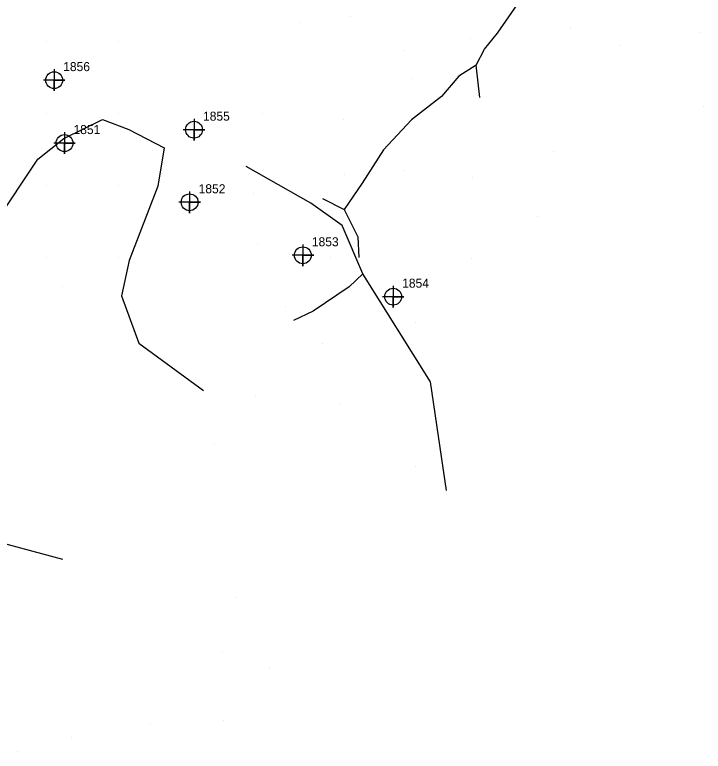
# Model space of a CAD drawing. Extents: x 2062781 to 2066835, y 358981 to 366501.
# Drawn here: x 2063986.2 to 2064177.3, y 360658.3 to 360862.8 of the extents above; entities that cross this region are included whole.
import ezdxf

# ---------------------------------------------------------------- set-up
doc = ezdxf.new("R2010")
doc.units = 0
for name, color, linetype in [('Exist DTM Regular Point CELL', 7, 'Continuous'), ('Exist DTM Regular Point Cogo Number', 7, 'Continuous'), ('PH Exist DTM Breakline', 7, 'Continuous'), ('PH Exist DTM Point', 7, 'Continuous')]:
    doc.layers.add(name, color=color, linetype=linetype)

msp = doc.modelspace()

# ---------------------------------------------------------------- linework, layer by layer
at = {"layer": 'Exist DTM Regular Point CELL'}
for points in [[(2063997.19, 360847.67), (2063997.19, 360841.67), (2063997.19, 360844.67), (2064000.19, 360844.67), (2063994.19, 360844.67)], [(2064036, 360833.91), (2064036, 360827.91), (2064036, 360830.91), (2064039, 360830.91), (2064033, 360830.91)], [(2064000.05, 360830.19), (2064000.05, 360824.19), (2064000.05, 360827.19), (2064003.05, 360827.19), (2063997.05, 360827.19)], [(2064034.78, 360813.76), (2064034.78, 360807.76), (2064034.78, 360810.76), (2064037.78, 360810.76), (2064031.78, 360810.76)], [(2064066.21, 360799.04), (2064066.21, 360793.04), (2064066.21, 360796.04), (2064069.21, 360796.04), (2064063.21, 360796.04)], [(2064091.27, 360787.55), (2064091.27, 360781.55), (2064091.27, 360784.55), (2064094.27, 360784.55), (2064088.27, 360784.55)]]:
    msp.add_lwpolyline(points, dxfattribs=at)
for centre in [(2063997.19, 360844.67), (2064036, 360830.91), (2064000.05, 360827.19), (2064034.78, 360810.76), (2064066.21, 360796.04), (2064091.27, 360784.55)]:
    msp.add_circle(centre, 2.34, dxfattribs=at)
at = {"layer": 'PH Exist DTM Breakline'}
for points in [[(2064115.35, 360839.89), (2064114.33, 360848.84), (2064116.6, 360853.22), (2064120.24, 360857.74), (2064126.5, 360866.73), (2064130.56, 360876.37)], [(2064114.33, 360848.84), (2064109.52, 360845.79), (2064104.7, 360840.08), (2064096.34, 360833.68), (2064088.55, 360825.34), (2064082.67, 360816.06), (2064077.65, 360808.79)], [(2063999.58, 360711.57), (2063972.79, 360718.76), (2063955.09, 360727.6), (2063933.02, 360738.67), (2063923.52, 360746.11), (2063918.7, 360754.97), (2063925.05, 360767.63), (2063932.38, 360783.08), (2063939.1, 360790.76), (2063953.8, 360793.42), (2063968.25, 360798.57), (2063980.79, 360805.01), (2063992.64, 360822.74), (2063999.86, 360828.51), (2064010.56, 360833.71), (2064017.94, 360830.97), (2064027.74, 360825.89), (2064025.97, 360815.26), (2064018.02, 360794.55), (2064015.86, 360784.76), (2064020.66, 360771.6), (2064038.6, 360758.54)], [(2064106.05, 360730.71), (2064101.62, 360760.95), (2064082.87, 360790.92), (2064077.08, 360804.3), (2064068.45, 360810.48), (2064050.43, 360820.72)], [(2064071.66, 360811.81), (2064077.65, 360808.79), (2064081.47, 360801.17), (2064081.78, 360795.39)], [(2064082.87, 360790.92), (2064079.07, 360787.3), (2064069.05, 360780.57), (2064063.64, 360777.96)]]:
    msp.add_lwpolyline(points, dxfattribs=at)
at = {"layer": 'PH Exist DTM Point'}
for p, q in [((2064079.38, 360862.3), (2064079.38, 360862.3)), ((2064065.4, 360860.74), (2064065.4, 360860.74)), ((2064140.58, 360858.99), (2064140.58, 360858.99)), ((2064176.49, 360857.83), (2064176.49, 360857.83)), ((2063995.13, 360855.38), (2063995.13, 360855.38)), ((2064015.13, 360855.38), (2064015.13, 360855.38)), ((2064112.76, 360856.17), (2064112.76, 360856.17)), ((2064154.24, 360854.36), (2064154.24, 360854.36)), ((2064094.53, 360852.86), (2064094.53, 360852.86)), ((2064096.28, 360845.07), (2064096.28, 360845.07)), ((2064177.34, 360837.4), (2064177.34, 360837.4)), ((2063995.13, 360835.38), (2063995.13, 360835.38)), ((2064015.13, 360835.38), (2064015.13, 360835.38)), ((2064055.13, 360835.38), (2064055.13, 360835.38)), ((2064077.4, 360833.77), (2064077.4, 360833.77)), ((2064135.88, 360824.92), (2064135.88, 360824.92)), ((2064077.88, 360818.48), (2064077.88, 360818.48)), ((2064094.43, 360819.52), (2064094.43, 360819.52)), ((2064113.28, 360817.66), (2064113.28, 360817.66)), ((2063995.13, 360815.38), (2063995.13, 360815.38)), ((2064015.13, 360815.38), (2064015.13, 360815.38)), ((2064052.43, 360813.18), (2064052.43, 360813.18)), ((2064131.26, 360806.94), (2064131.26, 360806.94)), ((2064053.62, 360798.97), (2064053.62, 360798.97)), ((2063995.13, 360795.38), (2063995.13, 360795.38)), ((2064015.13, 360795.38), (2064015.13, 360795.38)), ((2064073.91, 360795.56), (2064073.91, 360795.56)), ((2064112.88, 360795.08), (2064112.88, 360795.08)), ((2064098.52, 360789.64), (2064098.52, 360789.64)), ((2063999.37, 360787.39), (2063999.37, 360787.39)), ((2064061.3, 360781.85), (2064061.3, 360781.85)), ((2064097.34, 360777.4), (2064097.34, 360777.4)), ((2064071.54, 360771.54), (2064071.54, 360771.54)), ((2064053.02, 360756.93), (2064053.02, 360756.93)), ((2064076.35, 360754.69), (2064076.35, 360754.69)), ((2064041.64, 360743.75), (2064041.64, 360743.75)), ((2064097.34, 360737.4), (2064097.34, 360737.4)), ((2064047.88, 360701.01), (2064047.88, 360701.01)), ((2064044.02, 360685.9), (2064044.02, 360685.9)), ((2064056.91, 360681.48), (2064056.91, 360681.48)), ((2064024.05, 360665.81), (2064024.05, 360665.81)), ((2064044.17, 360666.8), (2064044.17, 360666.8)), ((2064001.87, 360662.18), (2064001.87, 360662.18)), ((2063987.02, 360658.35), (2063987.02, 360658.35))]:
    msp.add_line(p, q, dxfattribs=at)

# ---------------------------------------------------------------- texts
at = {"layer": 'Exist DTM Regular Point Cogo Number'}
for s, p in [('1856', (2063999.69, 360847.17)), ('1856', (2063999.69, 360847.17)), ('1856', (2063999.69, 360847.17)), ('1855', (2064038.5, 360833.41)), ('1855', (2064038.5, 360833.41)), ('1855', (2064038.5, 360833.41)), ('1851', (2064002.55, 360829.69)), ('1851', (2064002.55, 360829.69)), ('1851', (2064002.55, 360829.69)), ('1852', (2064037.28, 360813.26)), ('1852', (2064037.28, 360813.26)), ('1852', (2064037.28, 360813.26)), ('1853', (2064068.71, 360798.54)), ('1853', (2064068.71, 360798.54)), ('1853', (2064068.71, 360798.54)), ('1854', (2064093.77, 360787.05)), ('1854', (2064093.77, 360787.05)), ('1854', (2064093.77, 360787.05))]:
    msp.add_text(s, height=2.5, dxfattribs=at).set_placement(p)

doc.saveas('drawing.dxf')
